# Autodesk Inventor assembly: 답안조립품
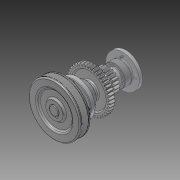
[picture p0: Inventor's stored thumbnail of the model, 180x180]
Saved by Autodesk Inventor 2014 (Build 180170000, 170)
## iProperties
Created: 2015-09
Part Number: 답안조립품
Document SubType Name: Assembly
Designer: Administrator
Author: Administrator
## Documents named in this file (14)
- C:\Users\Administrator\Desktop\450907V1042\답안조립품.iam
- C:\Users\Administrator\Desktop\450907V1042\1-본체.ipt
- C:\Users\Administrator\Desktop\450907V1042\V-벨트풀리.ipt
- C:\Users\Administrator\Desktop\450907V1042\뒤커버.ipt
- C:\Users\Administrator\Desktop\450907V1042\멈춤나사 - M4x10.ipt
- C:\Users\Administrator\Desktop\450907V1042\베어링 6203.ipt
- C:\Users\Administrator\Desktop\450907V1042\볼트 M3 x 8.ipt
- C:\Users\Administrator\Desktop\450907V1042\볼트 M3 x 10.ipt
- C:\Users\Administrator\Desktop\450907V1042\스퍼기어.ipt
- C:\Users\Administrator\Desktop\450907V1042\앞커버.ipt
- C:\Users\Administrator\Desktop\450907V1042\오일 실 17 32 8.ipt
- C:\Users\Administrator\Desktop\450907V1042\축.ipt
- C:\Users\Administrator\Desktop\450907V1042\키 - 5 x 5 x 18.ipt
- C:\Users\Administrator\Desktop\450907V1042\키 - 6 x 6 x 22.ipt
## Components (4 placed, 4 different names)
1. 1-본체:1
2. V-벨트풀리:1
3. ISO 4762 M3 x 8:1
4. ISO 4762 M3 x 10:1
